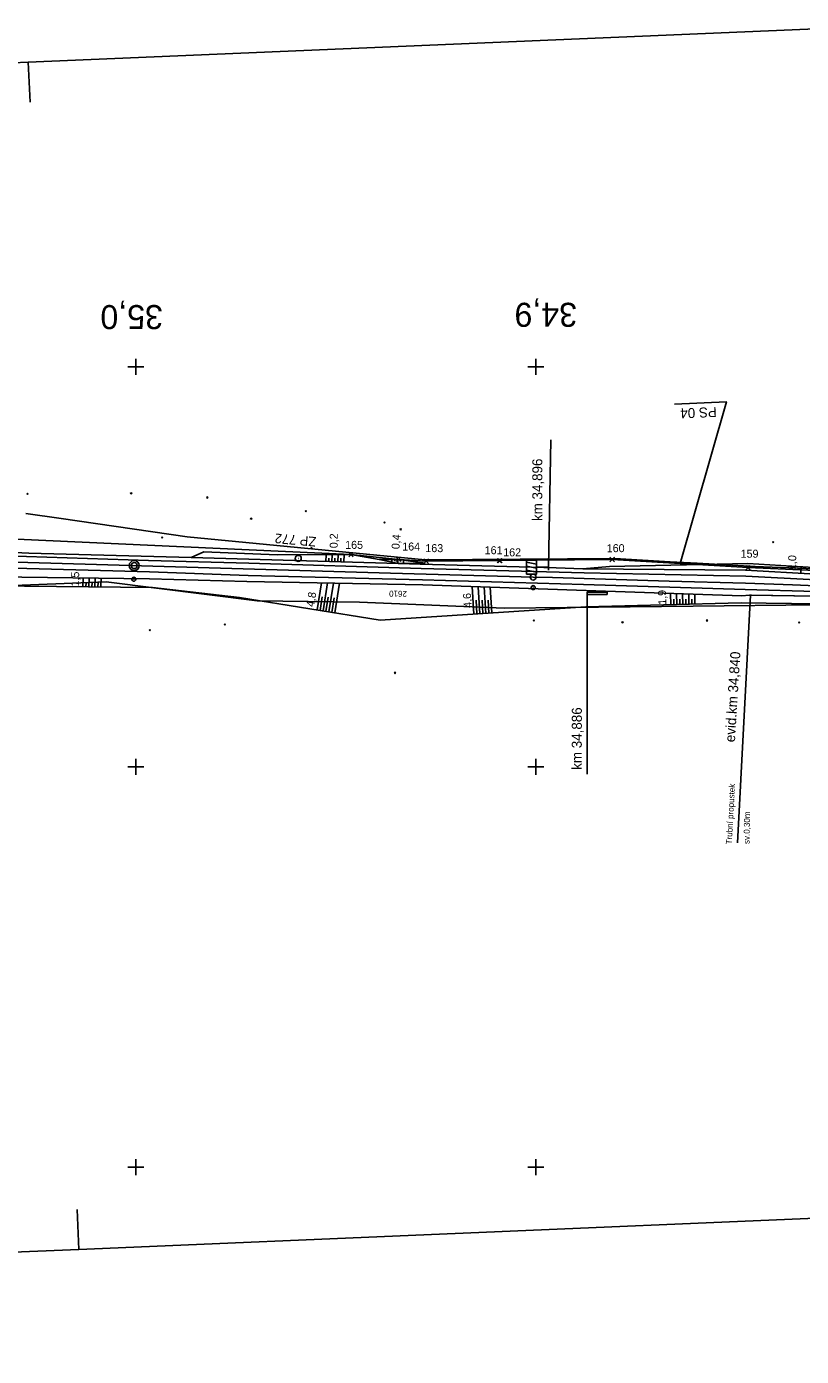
# Model space of a CAD drawing. Extents: x -806456 to -805395, y -1150847 to -1150506.
# Drawn here: x -805827.3 to -805633.7, y -1150847.3 to -1150515 of the extents above; entities that cross this region are included whole.
import ezdxf

# ---------------------------------------------------------------- set-up
doc = ezdxf.new("R2010")
doc.units = 0
for name, color, linetype in [('0381KM032-037P - Vrstva 1', 7, 'Continuous'), ('0381KM032-037P - Vrstva 19', 7, 'Continuous'), ('0381KM032-037P - Vrstva 4', 7, 'Continuous'), ('0381KM032-037P - Vrstva 48', 7, 'Continuous'), ('0381KM032-037P - Vrstva 49', 7, 'Continuous'), ('0381KM032-037P - Vrstva 57', 7, 'Continuous'), ('0381KM032-037P - Vrstva 7', 7, 'Continuous'), ('0381KM032-037P - Vrstva 9', 7, 'Continuous'), ('Default', 7, 'Continuous'), ('formát', 7, 'Continuous'), ('hran DP - hran DP', 7, 'Continuous'), ('krizky_1000 - Vrstva 1', 7, 'Continuous'), ('PSR_C2_2_Lomove_body_Vimperk - Vrstva 60', 7, 'Continuous'), ('PSR_C2_2_trasa_Vimperk - Kabelová trasa', 7, 'Continuous'), ('SOPS', 7, 'Continuous'), ('vyt_sit - stávající', 7, 'Continuous')]:
    doc.layers.add(name, color=color, linetype=linetype)

msp = doc.modelspace()

# ---------------------------------------------------------------- linework, layer by layer
at = {"layer": '0381KM032-037P - Vrstva 1'}
for points in [[(-805647.61, -1150654.06), (-805666.7, -1150653.55), (-805695.88, -1150652.69), (-805700.7, -1150652.54), (-805736.3, -1150651.55), (-805773.14, -1150650.48), (-805809.82, -1150649.4), (-805847.04, -1150648.36), (-805872.37, -1150647.65)], [(-805607.93, -1150656.05), (-805622.11, -1150655.05), (-805635.9, -1150654.45), (-805647.61, -1150654.06)]]:
    msp.add_lwpolyline(points, dxfattribs=at)
at = {"layer": '0381KM032-037P - Vrstva 19'}
for p, q in [((-805646.42, -1150657.11), (-805649.68, -1150718.98)), ((-805646.66, -1150657.1), (-805646.15, -1150657.11))]:
    msp.add_line(p, q, dxfattribs=at)
for points in [[(-805646.66, -1150657.1), (-805646.66, -1150657.1), (-805646.57, -1150657.13)], [(-805646.27, -1150657.1), (-805646.15, -1150657.11), (-805646.15, -1150657.11)]]:
    msp.add_lwpolyline(points, dxfattribs=at)
msp.add_ellipse((-805646.42, -1150657.11), major_axis=(0.15, 0.019), ratio=0.46044, start_param=6.207328, end_param=9.448235, dxfattribs=at)
at = {"layer": '0381KM032-037P - Vrstva 4'}
msp.add_line((-805728.9, -1150649.35), (-805734.36, -1150649.18), dxfattribs=at)
for points in [[(-805734.36, -1150649.18), (-805786.14, -1150647.68), (-805826.72, -1150646.54), (-805841.05, -1150645.92), (-805859.62, -1150645.3), (-805883.54, -1150644.38), (-805898.84, -1150644.02), (-805920.59, -1150645.08)], [(-805687.98, -1150651.47), (-805728.71, -1150650.4), (-805771.75, -1150649.09), (-805796.82, -1150648.44), (-805827.25, -1150647.42), (-805868.08, -1150645.94), (-805883.57, -1150645.79), (-805899.1, -1150645.56), (-805920.66, -1150646.24), (-805923.83, -1150646.61)], [(-805688.15, -1150654.42), (-805728.36, -1150653.2), (-805771.94, -1150652.19), (-805796.53, -1150651.28), (-805827.23, -1150650.42), (-805883.58, -1150648.86), (-805898.54, -1150648.68), (-805920.02, -1150649.65), (-805923.42, -1150649.97)], [(-805687.42, -1150655.93), (-805728.29, -1150654.47), (-805772.22, -1150653.64), (-805796.51, -1150653.02), (-805828.44, -1150652.6), (-805870.39, -1150650.22), (-805873.51, -1150650.39), (-805883.54, -1150650.55), (-805898.37, -1150650.08), (-805919.92, -1150650.63), (-805923.37, -1150650.9)], [(-805688.26, -1150650.5), (-805694.92, -1150650.2), (-805728.9, -1150649.35)], [(-805485.85, -1150681.76), (-805498.96, -1150678.92), (-805510.6, -1150675.66), (-805525.22, -1150671.48), (-805544.53, -1150665.72), (-805562.31, -1150661.11), (-805574.56, -1150658.15), (-805590.74, -1150655.42), (-805602.22, -1150654.14), (-805617.62, -1150652.74), (-805630.08, -1150651.83), (-805647.65, -1150650.8), (-805688.26, -1150650.5)], [(-805423.97, -1150686.92), (-805425.51, -1150687.49), (-805433.17, -1150688.49), (-805447.58, -1150687.79), (-805460.54, -1150686.52), (-805473.03, -1150684.97), (-805486, -1150682.53), (-805499.06, -1150679.64), (-805510.93, -1150676.58), (-805525.41, -1150672.29), (-805545.14, -1150666.47), (-805562.36, -1150661.85), (-805574.71, -1150659.28), (-805590.7, -1150656.46), (-805602.42, -1150654.96), (-805617.57, -1150653.8), (-805630.08, -1150653.28), (-805647.6, -1150652.35), (-805687.98, -1150651.47)], [(-805425.98, -1150691.47), (-805433.13, -1150691.22), (-805447.47, -1150690.71), (-805460.74, -1150689.57), (-805473.54, -1150687.87), (-805486.2, -1150685.62), (-805499.7, -1150682.42), (-805511.82, -1150679.35), (-805526.11, -1150675.23), (-805545.84, -1150669.48), (-805563.16, -1150664.96), (-805575.57, -1150662.2), (-805590.62, -1150659.46), (-805602.86, -1150658.06), (-805617.64, -1150656.78), (-805630.16, -1150656.16), (-805647.73, -1150655.65), (-805688.15, -1150654.42)], [(-805425.41, -1150692.47), (-805425.98, -1150691.47), (-805433.11, -1150692.35), (-805447.61, -1150691.82), (-805460.9, -1150690.59), (-805473.67, -1150688.98), (-805486.26, -1150686.57), (-805500.08, -1150683.65), (-805512.15, -1150680.12), (-805526.27, -1150676.26), (-805545.98, -1150670.57), (-805563.42, -1150665.87), (-805575.79, -1150663.12), (-805590.93, -1150660.59), (-805603.28, -1150659.09), (-805617.92, -1150657.97), (-805630.11, -1150657.32), (-805646.66, -1150657.1), (-805648.58, -1150657.2), (-805687.42, -1150655.93)]]:
    msp.add_lwpolyline(points, dxfattribs=at)
at = {"layer": '0381KM032-037P - Vrstva 48'}
for p, q in [((-805752.48, -1150648.66), (-805752.44, -1150646.97)), ((-805750.98, -1150648.7), (-805750.94, -1150646.96)), ((-805749.49, -1150648.74), (-805749.43, -1150646.96)), ((-805747.99, -1150648.79), (-805747.93, -1150646.95)), ((-805751.73, -1150648.68), (-805751.71, -1150647.82)), ((-805750.24, -1150648.72), (-805750.21, -1150647.84)), ((-805748.74, -1150648.77), (-805748.71, -1150647.86)), ((-805736.02, -1150648.12), (-805736.01, -1150648.83)), ((-805735.27, -1150648.12), (-805735.26, -1150648.56)), ((-805734.52, -1150648.12), (-805734.51, -1150649.15)), ((-805733.77, -1150648.2), (-805733.84, -1150648.69)), ((-805733.03, -1150648.31), (-805733.15, -1150649.17)), ((-805633.83, -1150651.61), (-805633.73, -1150649.96)), ((-805813.18, -1150654.95), (-805813.15, -1150652.8)), ((-805812.43, -1150654.96), (-805812.41, -1150653.89)), ((-805811.68, -1150654.97), (-805811.65, -1150652.82)), ((-805810.93, -1150654.98), (-805810.91, -1150653.91)), ((-805810.18, -1150654.99), (-805810.15, -1150652.84)), ((-805809.43, -1150654.99), (-805809.41, -1150653.92)), ((-805808.68, -1150655), (-805808.65, -1150652.86)), ((-805754.68, -1150660.78), (-805753.59, -1150653.99)), ((-805753.2, -1150661.01), (-805752.08, -1150654.02)), ((-805751.72, -1150661.25), (-805750.56, -1150654.05)), ((-805750.24, -1150661.49), (-805749.05, -1150654.08)), ((-805715.49, -1150661.81), (-805715.93, -1150654.91)), ((-805713.99, -1150661.71), (-805714.42, -1150654.97)), ((-805712.5, -1150661.62), (-805712.92, -1150655.02)), ((-805711, -1150661.52), (-805711.41, -1150655.07)), ((-805666.28, -1150659.46), (-805666.35, -1150656.62)), ((-805664.78, -1150659.42), (-805664.85, -1150656.67)), ((-805663.28, -1150659.38), (-805663.35, -1150656.72)), ((-805661.78, -1150659.34), (-805661.85, -1150656.77)), ((-805660.28, -1150659.3), (-805660.35, -1150656.81)), ((-805753.94, -1150660.89), (-805753.39, -1150657.45)), ((-805752.46, -1150661.13), (-805751.89, -1150657.58)), ((-805750.98, -1150661.37), (-805750.39, -1150657.72)), ((-805714.74, -1150661.76), (-805714.96, -1150658.35)), ((-805713.24, -1150661.67), (-805713.46, -1150658.33)), ((-805711.75, -1150661.57), (-805711.96, -1150658.31)), ((-805665.53, -1150659.44), (-805665.57, -1150658.04)), ((-805664.03, -1150659.4), (-805664.07, -1150658.04)), ((-805662.53, -1150659.36), (-805662.57, -1150658.05)), ((-805661.03, -1150659.32), (-805661.07, -1150658.05))]:
    msp.add_line(p, q, dxfattribs=at)
at = {"layer": '0381KM032-037P - Vrstva 49'}
for p, q in [((-805827.2, -1150631.55), (-805826.85, -1150631.9)), ((-805827.2, -1150631.9), (-805826.85, -1150631.55)), ((-805801.28, -1150631.44), (-805800.93, -1150631.8)), ((-805801.28, -1150631.8), (-805800.93, -1150631.44)), ((-805782.28, -1150632.48), (-805781.92, -1150632.83)), ((-805782.28, -1150632.83), (-805781.92, -1150632.48)), ((-805757.67, -1150635.89), (-805757.32, -1150636.25)), ((-805757.67, -1150636.25), (-805757.32, -1150635.89)), ((-805770.97, -1150637.78), (-805771.33, -1150638.14)), ((-805771.33, -1150637.78), (-805770.97, -1150638.13)), ((-805738.02, -1150638.73), (-805737.67, -1150639.09)), ((-805738.02, -1150639.09), (-805737.67, -1150638.73)), ((-805733.63, -1150640.45), (-805733.99, -1150640.81)), ((-805733.99, -1150640.45), (-805733.63, -1150640.81)), ((-805793.18, -1150642.5), (-805793.53, -1150642.85)), ((-805793.53, -1150642.5), (-805793.18, -1150642.85)), ((-805640.56, -1150643.67), (-805640.92, -1150644.02)), ((-805640.92, -1150643.67), (-805640.56, -1150644.02)), ((-805700.33, -1150663.23), (-805700.68, -1150663.59)), ((-805700.68, -1150663.23), (-805700.33, -1150663.58)), ((-805678.21, -1150663.68), (-805678.56, -1150664.04)), ((-805678.56, -1150663.69), (-805678.21, -1150664.04)), ((-805657.1, -1150663.22), (-805657.46, -1150663.57)), ((-805657.46, -1150663.22), (-805657.1, -1150663.57)), ((-805634.06, -1150663.7), (-805634.41, -1150664.05)), ((-805634.41, -1150663.7), (-805634.05, -1150664.05)), ((-805796.29, -1150665.66), (-805796.64, -1150666.01)), ((-805796.64, -1150665.66), (-805796.29, -1150666.01)), ((-805777.92, -1150664.26), (-805777.56, -1150664.61)), ((-805777.56, -1150664.26), (-805777.91, -1150664.61)), ((-805735.04, -1150676.33), (-805735.39, -1150676.68)), ((-805735.39, -1150676.33), (-805735.04, -1150676.68))]:
    msp.add_line(p, q, dxfattribs=at)
for points in [[(-805786.14, -1150647.68), (-805826.72, -1150646.54), (-805841.05, -1150645.92)], [(-805786.14, -1150647.68), (-805782.97, -1150646.21), (-805764.63, -1150647), (-805746.23, -1150646.95), (-805739.21, -1150648.13), (-805734.36, -1150649.18), (-805727.71, -1150649.08)], [(-805687.42, -1150655.93), (-805728.29, -1150654.47), (-805772.22, -1150653.64), (-805796.51, -1150653.02), (-805828.44, -1150652.6), (-805870.39, -1150650.22)], [(-805687.58, -1150660.02), (-805738.95, -1150663.31), (-805774.06, -1150657.65), (-805795.8, -1150655.14), (-805835.84, -1150654.7), (-805870.36, -1150656.71), (-805870.39, -1150650.22)], [(-805734.36, -1150649.18), (-805786.14, -1150647.68)], [(-805727.71, -1150649.08), (-805734.34, -1150648.12), (-805739.21, -1150648.13)], [(-805602.19, -1150651.94), (-805630.54, -1150650.16), (-805647.04, -1150649.14), (-805681.66, -1150649.9), (-805688.26, -1150650.5)], [(-805423.97, -1150686.92), (-805433.1, -1150687.91), (-805447.34, -1150686.91), (-805460.49, -1150686.09), (-805485.85, -1150681.76), (-805498.96, -1150678.92), (-805510.6, -1150675.66), (-805525.22, -1150671.48), (-805544.53, -1150665.72), (-805562.31, -1150661.11), (-805571.99, -1150658.79), (-805574.56, -1150658.15), (-805590.74, -1150655.42), (-805602.22, -1150654.14), (-805617.62, -1150652.74), (-805630.08, -1150651.83), (-805647.65, -1150650.8), (-805688.26, -1150650.5)], [(-805425.41, -1150692.47), (-805425.98, -1150691.47), (-805433.11, -1150692.35), (-805447.61, -1150691.82), (-805460.9, -1150690.59), (-805473.67, -1150688.98), (-805486.26, -1150686.57), (-805500.08, -1150683.65), (-805512.15, -1150680.12), (-805526.27, -1150676.26), (-805545.98, -1150670.57), (-805563.42, -1150665.87), (-805575.79, -1150663.12), (-805590.93, -1150660.59), (-805603.28, -1150659.09), (-805617.92, -1150657.97), (-805630.11, -1150657.32), (-805646.15, -1150657.11), (-805646.27, -1150657.1), (-805646.57, -1150657.13), (-805646.66, -1150657.1), (-805648.58, -1150657.2), (-805687.42, -1150655.93)], [(-805428.8, -1150698.61), (-805426.99, -1150695.45), (-805434.79, -1150695.76), (-805452.59, -1150694.8), (-805474.79, -1150691.73), (-805486.9, -1150690.07), (-805513.13, -1150683.83), (-805526.69, -1150679.91), (-805538.18, -1150675.92), (-805547.05, -1150672.92), (-805563.97, -1150668.42), (-805576.87, -1150665.35), (-805586.81, -1150663.24), (-805590.73, -1150662.74), (-805601.92, -1150661.35), (-805629.88, -1150659.22), (-805648.74, -1150658.99), (-805687.58, -1150660.02)]]:
    msp.add_lwpolyline(points, dxfattribs=at)
at = {"layer": '0381KM032-037P - Vrstva 7'}
for p, q in [((-805696.85, -1150650.05), (-805696.3, -1150618.26)), ((-805699.85, -1150649.3), (-805702.35, -1150648.8)), ((-805702.35, -1150649.8), (-805699.85, -1150650.3)), ((-805696.85, -1150650.8), (-805696.85, -1150649.3)), ((-805800.52, -1150653.09), (-805800.42, -1150653.09)), ((-805699.85, -1150651.3), (-805702.35, -1150650.8)), ((-805700.75, -1150655.18), (-805700.65, -1150655.18))]:
    msp.add_line(p, q, dxfattribs=at)
msp.add_lwpolyline([(-805696.85, -1150650.05), (-805699.85, -1150650.05), (-805699.85, -1150648.3), (-805702.35, -1150648.3), (-805702.35, -1150651.8), (-805699.85, -1150651.8), (-805699.85, -1150650.05)], dxfattribs=at)
for centre, radius in [((-805800.37, -1150649.68), 1.25), ((-805800.37, -1150649.68), 0.752), ((-805800.47, -1150653.09), 0.5), ((-805700.7, -1150652.54), 0.75), ((-805700.7, -1150655.18), 0.5)]:
    msp.add_circle(centre, radius, dxfattribs=at)
at = {"layer": '0381KM032-037P - Vrstva 9'}
for p, q in [((-805682.22, -1150656.32), (-805687.22, -1150656.31)), ((-805687.22, -1150656.31), (-805687.22, -1150656.91)), ((-805687.22, -1150656.61), (-805687.22, -1150701.82)), ((-805687.22, -1150656.91), (-805682.22, -1150656.92)), ((-805687.22, -1150656.91), (-805687.22, -1150657.51)), ((-805682.22, -1150656.92), (-805682.22, -1150656.32))]:
    msp.add_line(p, q, dxfattribs=at)
at = {"layer": 'formát'}
for p, q in [((-805617.02, -1150514.97), (-805826.83, -1150523.88)), ((-805826.83, -1150523.88), (-806456.26, -1150550.6)), ((-805826.83, -1150523.88), (-805826.4, -1150533.87)), ((-805814.66, -1150810.62), (-805814.23, -1150820.61)), ((-805604.42, -1150811.7), (-805814.23, -1150820.61)), ((-805814.23, -1150820.61), (-806443.66, -1150847.33))]:
    msp.add_line(p, q, dxfattribs=at)
at = {"layer": 'hran DP - hran DP'}
for p, q in [((-805827.46, -1150636.65), (-805818.65, -1150637.92)), ((-805818.65, -1150637.92), (-805787.18, -1150642.48)), ((-805787.18, -1150642.48), (-805727.67, -1150648.26)), ((-805727.67, -1150648.26), (-805680.28, -1150647.93)), ((-805680.28, -1150647.93), (-805666.44, -1150648.72)), ((-805666.44, -1150648.72), (-805659.71, -1150649.1)), ((-805659.71, -1150649.1), (-805655.39, -1150649.35)), ((-805655.39, -1150649.35), (-805645.21, -1150649.93)), ((-805645.21, -1150649.93), (-805611.34, -1150651.29)), ((-805807.41, -1150653.77), (-805838.22, -1150654.94)), ((-805769.65, -1150658.51), (-805807.41, -1150653.77)), ((-805744.09, -1150658.84), (-805769.65, -1150658.51)), ((-805707.95, -1150660.33), (-805744.09, -1150658.84)), ((-805660.75, -1150659.79), (-805707.95, -1150660.33)), ((-805629.87, -1150659.45), (-805660.75, -1150659.79))]:
    msp.add_line(p, q, dxfattribs=at)
at = {"layer": 'krizky_1000 - Vrstva 1'}
for points in [[(-805802, -1150600), (-805798, -1150600)], [(-805800, -1150598), (-805800, -1150602)], [(-805702, -1150600), (-805698, -1150600)], [(-805700, -1150598), (-805700, -1150602)], [(-805802, -1150700), (-805798, -1150700)], [(-805800, -1150698), (-805800, -1150702)], [(-805702, -1150700), (-805698, -1150700)], [(-805700, -1150698), (-805700, -1150702)], [(-805802, -1150800), (-805798, -1150800)], [(-805800, -1150798), (-805800, -1150802)], [(-805702, -1150800), (-805698, -1150800)], [(-805700, -1150798), (-805700, -1150802)]]:
    msp.add_lwpolyline(points, dxfattribs=at)
at = {"layer": 'PSR_C2_2_Lomove_body_Vimperk - Vrstva 60'}
for p, q in [((-805746.78, -1150647.5), (-805745.68, -1150646.4)), ((-805745.68, -1150647.5), (-805746.78, -1150646.4)), ((-805734.89, -1150648.67), (-805733.79, -1150647.57)), ((-805733.79, -1150648.67), (-805734.89, -1150647.57)), ((-805727.98, -1150649.13), (-805726.88, -1150648.03)), ((-805726.88, -1150649.13), (-805727.98, -1150648.03)), ((-805709.7, -1150648.99), (-805708.6, -1150647.89)), ((-805708.6, -1150648.99), (-805709.7, -1150647.89)), ((-805709.54, -1150648.99), (-805708.44, -1150647.89)), ((-805708.44, -1150648.99), (-805709.54, -1150647.89)), ((-805681.51, -1150648.71), (-805680.41, -1150647.61)), ((-805680.41, -1150648.71), (-805681.51, -1150647.61)), ((-805647.56, -1150650.73), (-805646.46, -1150649.63)), ((-805646.46, -1150650.73), (-805647.56, -1150649.63))]:
    msp.add_line(p, q, dxfattribs=at)
at = {"layer": 'PSR_C2_2_trasa_Vimperk - Kabelová trasa'}
for points in [[(-805871.58, -1150644.84), (-805841.67, -1150645.26), (-805829.69, -1150643.07), (-805746.23, -1150646.95), (-805734.34, -1150648.12), (-805727.43, -1150648.58), (-805708.99, -1150648.44)], [(-805709.15, -1150648.44), (-805680.96, -1150648.16), (-805647.01, -1150650.18)], [(-805647.01, -1150650.18), (-805632.04, -1150650.81), (-805624.23, -1150651.13)]]:
    msp.add_lwpolyline(points, dxfattribs=at)
at = {"layer": 'SOPS'}
msp.add_lwpolyline([(-805663.99, -1150649.17), (-805652.43, -1150608.73), (-805665.43, -1150609.31)], dxfattribs=at)
at = {"layer": 'vyt_sit - stávající'}
msp.add_line((-805759.43, -1150647.88), (-805759.33, -1150647.88), dxfattribs=at)
msp.add_circle((-805759.38, -1150647.88), 0.756, dxfattribs=at)

# ---------------------------------------------------------------- texts
at = {"layer": '0381KM032-037P - Vrstva 19'}
for s, height, rotation, p in [('evid.km 34,840', 2.5, 86.4544, (-805650.31, -1150693.88)), ('Trubní propustek', 1.5, 86.8495, (-805651.08, -1150719.38)), ('sv.0,30m', 1.5, 88.8723, (-805646.65, -1150719.28))]:
    msp.add_text(s, height=height, rotation=rotation, dxfattribs=at).set_placement(p)
at = {"layer": '0381KM032-037P - Vrstva 48'}
for s, rotation, p in [('0,2', 90.1588, (-805749.52, -1150645.34)), ('0,4', 85.1177, (-805734.12, -1150645.65)), ('1,0', 86.4602, (-805635.16, -1150650.83)), ('1,5', 89.3704, (-805814.15, -1150654.92)), ('4,8', 80.8487, (-805755.45, -1150660.12)), ('4,6', 93.6586, (-805716.04, -1150660.2)), ('1,9', 91.5281, (-805667.43, -1150659.46))]:
    msp.add_text(s, height=2, rotation=rotation, dxfattribs=at).set_placement(p)
at = {"layer": '0381KM032-037P - Vrstva 57'}
msp.add_text('2610', height=1.5, rotation=179.2665, dxfattribs=at).set_placement((-805732.22, -1150656.01))
at = {"layer": '0381KM032-037P - Vrstva 7'}
for s, height, rotation, p in [('35,0', 6, 180, (-805793.2, -1150584.57)), ('34,9', 6, 180, (-805689.73, -1150584)), ('km 34,896', 2.5, 90, (-805698.41, -1150638.55))]:
    msp.add_text(s, height=height, rotation=rotation, dxfattribs=at).set_placement(p)
at = {"layer": '0381KM032-037P - Vrstva 9'}
msp.add_text('km 34,886', height=2.5, rotation=89.869, dxfattribs=at).set_placement((-805688.57, -1150700.72))
at = {"layer": 'Default'}
for s, p in [('165', (-805747.67, -1150645.5)), ('164', (-805733.41, -1150645.91)), ('163', (-805727.64, -1150646.32)), ('161', (-805712.82, -1150646.84)), ('162', (-805708.18, -1150647.37)), ('160', (-805682.32, -1150646.33)), ('159', (-805648.87, -1150647.71))]:
    msp.add_text(s, height=2, dxfattribs=at).set_placement(p)
at = {"layer": 'SOPS'}
msp.add_text('PS 04', height=2.5, rotation=182.4308, dxfattribs=at).set_placement((-805654.89, -1150610.03))
at = {"layer": 'vyt_sit - stávající'}
msp.add_text('ŽP 772', height=2.4, rotation=175, dxfattribs=at).set_placement((-805754.82, -1150642.56))

doc.saveas('drawing.dxf')
